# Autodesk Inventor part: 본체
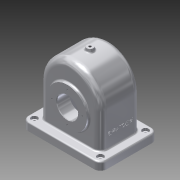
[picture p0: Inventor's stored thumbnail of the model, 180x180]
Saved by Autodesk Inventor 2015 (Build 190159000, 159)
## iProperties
Created: 2016-10
Part Number: 본체
Material: 알루미늄 6061
Document SubType Name: Modeling
Designer: pc01
Density: 2.7 g/cm^3
Appearance: 알루미늄 - 평지
Mass: 1143.78 g
Surface Area: 1196.99 cm^2
Volume: 423.621 cm^3
Author: pc01
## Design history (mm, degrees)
sketch "스케치1"
  geometry: L1 (-58, 80)-(58, 80); L2 (58, 80)-(58, 0); L3 (58, 0)-(-58, 0); L4 (-58, 0)-(-58, 80); C1 r 58 at (0, 80); 2 further points
  constraints: 8 end point, 2 parallel, 1 centre point, 1 coincident, 1 horizontal, 1 midpoint, 1 perpendicular, 1 vertical alignment
  dimensions: "d0" = 80 distance from line of L1 point (0, 0); "d1" = 116 distance of L1.start L1.end; "d2" = 80 distance of L3.end L1.start; "d3" = 116 diameter of C1
extrude "돌출1" new body sketch "스케치1" stored distance "d4" = 77; taper "d5" = 0 deg
sketch "스케치2"
  geometry: L1 (-17, 16.5)-(133, 16.5); L2 (133, 16.5)-(133, -93.5); L3 (133, -93.5)-(-17, -93.5); L4 (-17, -93.5)-(-17, 16.5); 1 further point
  constraints: 8 end point, 2 parallel, 1 horizontal, 1 perpendicular
  dimensions: "d6" = 150 distance of L1.start L1.end; "d7" = 110 distance of L1.end L2.end; "d8" = 55 distance from line of point (58, -38.5) L1; "d9" = 75 distance from line of point (58, -38.5) L4
extrude "돌출2" join sketch "스케치2" distance "d10" = 15; taper "d11" = 0 deg
fillet "모깎기1" dims "d12" = 13
sketch "스케치3"
  geometry: L1 (0, -55)-(0, 55) reference; L2 (80, 33.5)-(0, 33.5); L3 (0, 33.5)-(0, -33.5); L4 (0, -33.5)-(80, -33.5); L5 (80, -33.5)-(80, 33.5); 1 further point
  constraints: 8 end point, 2 midpoint, 2 parallel, 1 horizontal, 1 perpendicular
  dimensions: "d21" = 67 distance of L2.end L3.end; "d22" = 80 distance between parallel lines of L1 L5
extrude "돌출3" cut sketch "스케치3" stored distance "d23" = 104; taper "d24" = 0 deg
sketch "스케치4"
  geometry: L1 (-52, 80)-(52, 80) reference; C1 r 52 at (0, 80); 2 further points
  constraints: 1 centre point, 1 coincident, 1 midpoint
  dimensions: "d25" = 104 diameter of C1
extrude "돌출4" cut sketch "스케치4" stored distance "d26" = 67; taper "d27" = 0 deg
sketch "스케치6"
  geometry: L1 (-75, 0)-(75, 0) reference; C1 r 37.5 at (0, 65); 2 further points
  constraints: 1 centre point, 1 midpoint, 1 vertical alignment
  dimensions: "d35" = 75 diameter of C1; "d36" = 65 distance of point (0, 0) C1.centre
extrude "돌출5" join sketch "스케치6" distance "d37" = 5; taper "d38" = 0 deg
node "작업 평면1"
sketch "스케치7"
  geometry: L1 (-75, 0)-(75, 0) reference; C1 r 31 at (0, 65); 2 further points
  constraints: 1 centre point, 1 midpoint, 1 vertical alignment
  dimensions: "d40" = 62 diameter of C1; "d41" = 65 distance from line of L1 C1.centre
extrude "돌출6" join sketch "스케치7" stored distance "d42" = 5; taper "d43" = 0 deg
sketch "스케치8"
  geometry: C1 r 37.5 at (0, 0) reference; C2 r 20 at (0, 0); 1 further point
  constraints: 1 centre point, 1 coincident
  dimensions: "d44" = 40 diameter of C2
extrude "돌출7" cut sketch "스케치8" stored distance "d45" = 24; taper "d46" = 0 deg
fillet "모깎기2" dims "d61" = 8
sketch "스케치13" dims "d80" = 58
  geometry: C1 r 37.5 at (0, 0) reference; 3 further points
  constraints: 2 vertical alignment, 1 coincident, 2 other
hole "구멍2" sketch "스케치13" at (0, 29) diameter "d81" = 2.459; stored, may be unused: countersink angle "d85" = 90 deg, drill point angle "d87" = 118 deg; dims "d82" = 6, "d83" = 4, "d84" = 2, "d86" = 8
sketch "스케치14" dims "d91" = 52
  geometry: C1 r 31 at (0, 0) reference; 3 further points
  constraints: 2 vertical alignment, 1 coincident, 2 other
hole "구멍3" sketch "스케치14" at (0, 26) diameter "d92" = 2.459; stored, may be unused: countersink angle "d96" = 90 deg, drill point angle "d98" = 118 deg; dims "d93" = 6, "d94" = 4, "d95" = 2, "d97" = 8
fillet "모깎기3" dims "d102" = 12
sketch "스케치15"
  geometry: L1 (-5, -16.5)-(121, -16.5) reference; L2 (133, -4.5)-(133, 81.5) reference; L3 (121, 93.5)-(-5, 93.5) reference; L4 (-17, 81.5)-(-17, -4.5) reference; L5 (103, 77)-(13, 77) reference; L6 (116, 13)-(116, 64) reference; L7 (13, 0)-(103, 0) reference; L8 (0, 64)-(0, 13) reference; A1 r 12 centre (-5, -4.5) between (-17, -4.5) and (-5, -16.5) reference; A2 r 12 centre (121, -4.5) between (121, -16.5) and (133, -4.5) reference; A3 r 12 centre (121, 81.5) between (133, 81.5) and (121, 93.5) reference; A4 r 12 centre (-5, 81.5) between (-5, 93.5) and (-17, 81.5) reference; A5 r 13 centre (103, 64) between (116, 64) and (103, 77) reference; A6 r 13 centre (103, 13) between (103, 0) and (116, 13) reference; A7 r 13 centre (13, 13) between (0, 13) and (13, 0) reference; A8 r 13 centre (13, 64) between (13, 77) and (0, 64) reference; 1 further point
hole "구멍4" sketch "스케치15" at (121, 81.5), (-5, 81.5), (-5, -4.5), (121, -4.5) diameter "d103" = 5; stored, may be unused: countersink angle "d107" = 90 deg, drill point angle "d109" = 0 deg; dims "d104" = 6, "d105" = 12, "d106" = 5, "d108" = 8
fillet "모깎기4" dims "d110" = 3
sketch "스케치17"
  geometry: L1 (4.5, 80)-(4.5, 15) reference; 2 further points
  constraints: 1 other
  dimensions: "d113" = 40 distance of point (43, 0) point (43, 40); "d114" = 38.5 distance from line of L1 point (43, 40)
feature "엠보싱1" sketch "스케치17" dims "d0" = 80, "d1" = 116, "d2" = 80, "d3" = 116, "d115" = 0.5, "d116" = 0
fillet "모깎기5" dims "d117" = 3
sketch "스케치18"
  geometry: L1 (134, 0)-(144, 0); L2 (144, 0)-(144, 6); L3 (144, 6)-(134, 7.763); L4 (134, 7.763)-(134, 0); L5 (124, 33.5)-(80, 33.5) reference; 1 further point
  constraints: 8 end point, 2 perpendicular, 1 horizontal
  dimensions: "d118" = 33.5 distance from line of L5 L1.end; "d119" = 12 diameter of L2.end L1; "d120" = 100 deg angle of L4 L3; "d121" = 144 distance of point (0, 0) L1.end; "d122" = 10 distance of L1.start L1.end
revolve "회전2" sketch "스케치18" stored, may be unused: angle "d123" = 90 deg
sketch "스케치19"
  geometry: C1 r 6 at (0, 0) reference; 1 further point
hole "구멍5" sketch "스케치19" at (0, 0) diameter "d124" = 4.459; stored, may be unused: countersink angle "d128" = 90 deg, drill point angle "d130" = 118 deg; dims "d125" = 100, "d126" = 4, "d127" = 2, "d129" = 12.8
fillet "모깎기6" dims "d131" = 3
chamfer "모따기1" distance "d132" = 1; stored, may be unused: second distance "d133" = 2, angle "d134" = 45 deg
chamfer "모따기2" distance "d135" = 1; stored, may be unused: second distance "d136" = 2, angle "d137" = 45 deg
sketch "스케치20"
  geometry: L1 (124, 33.5)-(80, 33.5) reference; L2 (85, 33.5)-(45, 33.5) reference; L3 (65, 33.5)-(65, 19.5); L4 (65, 19.5)-(93, 19.5); L5 (93, 19.5)-(104.747, 33.5); L6 (104.747, 33.5)-(65, 33.5); L7 (80, 25.5)-(80, 33.5) reference; L8 (86, 43.5)-(44, 43.5) reference; 1 further point
  constraints: 8 end point, 2 perpendicular, 1 midpoint, 1 point on line, 1 vertical
  dimensions: "d138" = 65 horizontal distance of point (0, 0) L3.end; "d139" = 24 distance from line of L3.end L8; "d140" = 50 deg angle of L5 L4; "d141" = 56 diameter of L4.end L3
revolve "회전3" sketch "스케치20" stored, may be unused: angle "d142" = 90 deg
sketch "스케치21"
  geometry: C1 r 20 at (0, 0) reference; 1 further point
extrude "돌출10" cut sketch "스케치21" stored distance "d143" = 10; taper "d144" = 0 deg
node "솔리드1"
pattern_circular "원형 패턴1" dims angle "d89" = 360 deg
pattern_circular "원형 패턴2" dims angle "d100" = 360 deg
node "투영된 루프2"
node "투영된 루프4"
node "투영된 루프5"
other parameters: "d39" = -87
